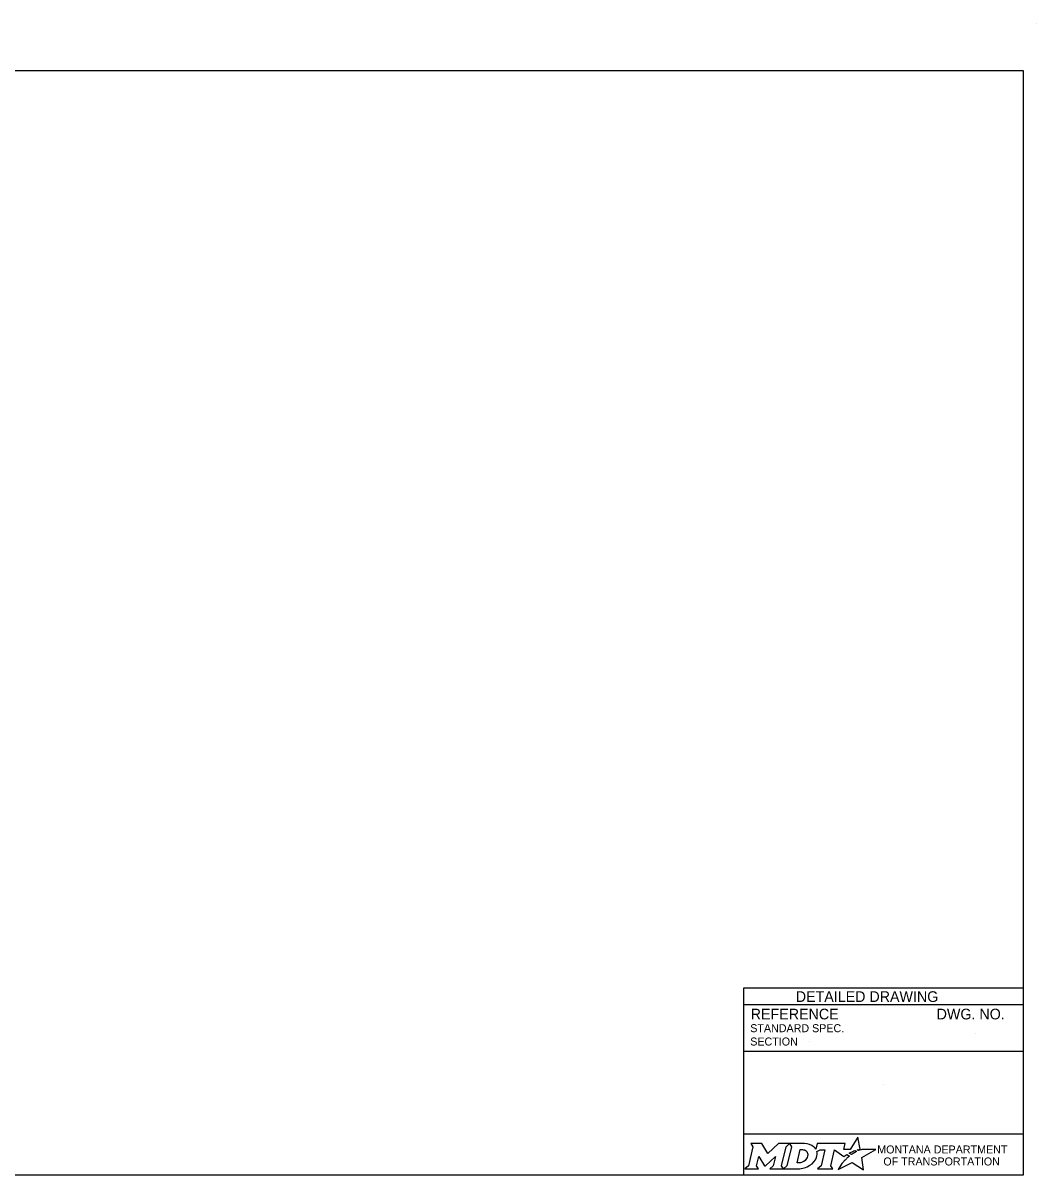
# Model space of a CAD drawing. Extents: x 49979.1 to 50021, y 49966.7 to 50011.4.
# Drawn here: x 50013.44 to 50021.04, y 49999.89 to 50008.52 of the extents above; entities that cross this region are included whole.
import ezdxf

# ---------------------------------------------------------------- set-up
doc = ezdxf.new("R2010")
doc.units = 0
for name, color, linetype in [('Default', 7, 'Continuous'), ('Level 1', 7, 'Continuous'), ('Level 4', 7, 'Continuous')]:
    doc.layers.add(name, color=color, linetype=linetype)

msp = doc.modelspace()

# ---------------------------------------------------------------- linework, layer by layer
at = {"layer": 'Default'}
for points in [[(50018.8933, 50000.1206), (50018.9074, 50000.0972), (50018.8739, 49999.9539), (50018.8482, 49999.9314), (50018.9498, 49999.9314), (50018.9363, 49999.9542), (50018.9525, 50000.0243), (50018.9962, 49999.9553), (50019.0015, 49999.9553), (50019.0766, 50000.0248), (50019.0602, 49999.9537), (50019.0355, 49999.9317), (50019.1371, 49999.9317), (50019.1233, 49999.955), (50019.1565, 50000.0974)], [(50019.1565, 50000.0974), (50019.1818, 50000.1206), (50019.0994, 50000.1206), (50019.0198, 50000.0476), (50018.9753, 50000.1203), (50018.8933, 50000.1206)], [(50019.2954, 50000.1206), (50019.1818, 50000.1206), (50019.1965, 50000.0977), (50019.1626, 49999.9539), (50019.1371, 49999.9317), (50019.2477, 49999.9317)], [(50019.7003, 50000.0679), (50019.69, 50000.0735), (50019.7016, 50000.0763), (50019.7132, 50000.0783), (50019.6958, 50000.1684), (50019.6363, 50000.0771), (50019.589, 50000.0764), (50019.5993, 50000.1205), (50019.3901, 50000.1206), (50019.38, 50000.0781), (50019.3742, 50000.0864)], [(50019.3194, 50000.0339), (50019.3182, 50000.0258), (50019.315, 50000.0165), (50019.3108, 50000.0083), (50019.3052, 50000.0008), (50019.2987, 49999.9939), (50019.2908, 49999.9876), (50019.2825, 49999.9829), (50019.2734, 49999.979), (50019.2643, 49999.9767), (50019.2551, 49999.9758), (50019.2392, 49999.9758), (50019.2628, 50000.0758), (50019.2788, 50000.0758), (50019.2864, 50000.0752), (50019.294, 50000.0733), (50019.3006, 50000.0703), (50019.3067, 50000.0661), (50019.3115, 50000.0611), (50019.3152, 50000.0551), (50019.3179, 50000.0489), (50019.3195, 50000.0415), (50019.3195, 50000.0385), (50019.3194, 50000.0339)], [(50019.3868, 50000.0615), (50019.4114, 50000.0746), (50019.4483, 50000.0746), (50019.4197, 49999.9541), (50019.3922, 49999.9314), (50019.5084, 49999.9314), (50019.4914, 49999.9543), (50019.5196, 50000.0745), (50019.5909, 50000.0228), (50019.612, 50000.0379), (50019.6317, 50000.027)], [(50019.5759, 49999.9711), (50019.5606, 49999.9467), (50019.5559, 49999.9392), (50019.5501, 49999.9306), (50019.5478, 49999.9263), (50019.6531, 49999.9794), (50019.737, 49999.9243), (50019.7239, 50000.017), (50019.8308, 50000.0754), (50019.7815, 50000.0762), (50019.7514, 50000.0766), (50019.7306, 50000.0769), (50019.7238, 50000.0754), (50019.7189, 50000.0742), (50019.7105, 50000.0719), (50019.7003, 50000.0679)], [(50019.6499, 50000.0403), (50019.6475, 50000.0386), (50019.6292, 50000.0482), (50019.6395, 50000.0539), (50019.6436, 50000.0561), (50019.6522, 50000.0601), (50019.6579, 50000.0627), (50019.6658, 50000.0657), (50019.6731, 50000.0684), (50019.6849, 50000.061), (50019.6809, 50000.0589), (50019.6763, 50000.0564), (50019.6721, 50000.0542), (50019.6671, 50000.0513), (50019.6652, 50000.0502), (50019.6625, 50000.0486), (50019.66, 50000.0472), (50019.6577, 50000.0456), (50019.6551, 50000.0438), (50019.6524, 50000.042), (50019.6499, 50000.0403)], [(50019.2934, 49999.939), (50019.3018, 49999.9416), (50019.3148, 49999.947), (50019.3352, 49999.958)], [(50019.5898, 49999.9872), (50019.5898, 49999.9872)]]:
    msp.add_lwpolyline(points, dxfattribs=at)
for centre, radius, start, end in [((50019.3185, 50000.0422), 0.0709, 339.53292, 15.85821), ((50019.2745, 50000.0595), 0.1183, 300.91025, 339.13831)]:
    msp.add_arc(centre, radius, start, end, dxfattribs=at)
for centre, major_axis, ratio, start_param, end_param in [((50019.2933, 50000.0732), (0.0834, -0.0037), 0.568097, 0.61298, 1.570796), ((50019.3489, 50000.0805), (0.0361, -0.0295), 0.469099, 1.225588, 1.570796), ((50019.6206, 50000.0173), (-0.0112, -0.0097), 0.021651, 3.157348, 6.283185), ((50019.5829, 49999.9791), (-0.00694, -0.00806), 0.008222, 0, 3.137361), ((50019.5996, 49999.9974), (-0.0098, -0.0102), 0.016458, 3.141593, 6.279097), ((50019.248, 50000.08), (0, 0.1484), 0.987302, 3.139398, 3.456847)]:
    msp.add_ellipse(centre, major_axis=major_axis, ratio=ratio, start_param=start_param, end_param=end_param, dxfattribs=at)
at = {"layer": 'Level 1'}
msp.add_line((50021.0378, 50008.5236), (50021.0378, 50008.5236), dxfattribs=at)
msp.add_lwpolyline([(50020.9378, 50008.1646), (50009.7374, 50008.1646), (50009.7374, 49999.8856), (50020.9378, 49999.8856)], close=True, dxfattribs=at)
at = {"layer": 'Level 4'}
for p, q in [((50020.9378, 50001.2856), (50018.8378, 50001.2856)), ((50018.8378, 50001.2856), (50018.8378, 49999.8856)), ((50020.9378, 50001.1606), (50018.8378, 50001.1606)), ((50020.5739, 50000.9455), (50020.5739, 50000.9455)), ((50020.9378, 50000.8106), (50018.8378, 50000.8106)), ((50019.3321, 50000.8861), (50019.3321, 50000.8861)), ((50019.8878, 50000.5615), (50019.8878, 50000.5615)), ((50020.9378, 50000.1925), (50018.8378, 50000.1925))]:
    msp.add_line(p, q, dxfattribs=at)

# ---------------------------------------------------------------- texts
at = {"layer": 'Default'}
for s, p in [('MONTANA DEPARTMENT', (50019.8403, 50000.0468)), ('OF TRANSPORTATION', (50019.8862, 49999.9568))]:
    msp.add_text(s, height=0.06, rotation=360, dxfattribs=at).set_placement(p)
at = {"layer": 'Level 4'}
for s, height, p in [('DETAILED DRAWING', 0.0799, (50019.2295, 50001.1831)), ('REFERENCE', 0.08, (50018.8914, 50001.0522)), ('DWG. NO.', 0.08, (50020.2856, 50001.0522)), ('STANDARD SPEC.', 0.06, (50018.8881, 50000.9562)), ('SECTION', 0.06, (50018.8881, 50000.8562))]:
    msp.add_text(s, height=height, dxfattribs=at).set_placement(p)

doc.saveas('drawing.dxf')
